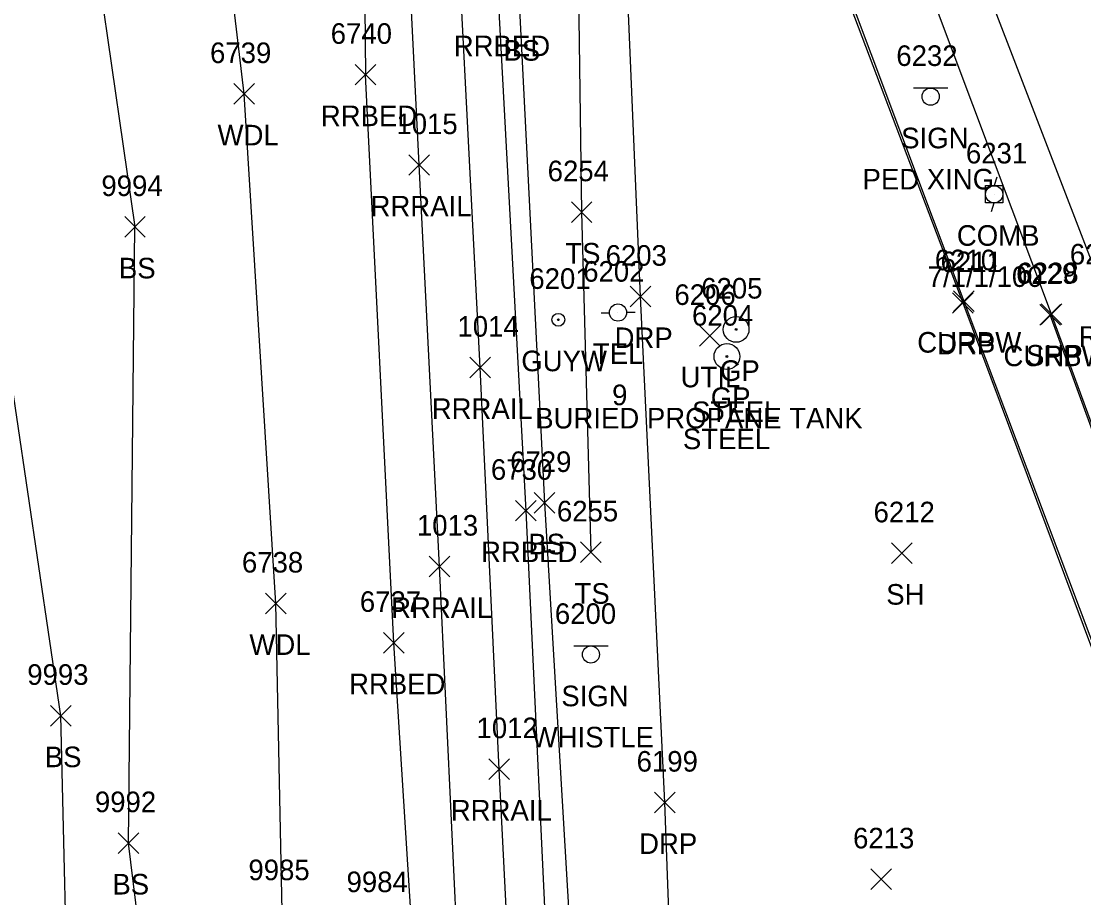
# Model space of a CAD drawing. Extents: x 1769141 to 1770817, y 735471 to 742405.
# Drawn here: x 1770145.7 to 1770248.9, y 740592.3 to 740677.5 of the extents above; entities that cross this region are included whole.
import ezdxf

# ---------------------------------------------------------------- set-up
doc = ezdxf.new("R2010")
doc.units = 0
for name, color, linetype in [('L_A', 7, 'Continuous'), ('L_I', 7, 'Continuous'), ('L_TIC', 7, 'Continuous'), ('LAWA', 7, 'Continuous'), ('LELB', 7, 'Continuous'), ('P_A', 7, 'Continuous'), ('P_I', 7, 'Continuous'), ('P_TIC', 7, 'Continuous'), ('PET', 7, 'Continuous'), ('PSP', 7, 'Continuous'), ('R_A', 7, 'Continuous'), ('R_C', 7, 'Continuous'), ('R_I', 7, 'Continuous'), ('R_TIC', 7, 'Continuous'), ('RC', 7, 'Continuous'), ('RDP', 7, 'Continuous'), ('RGP', 7, 'Continuous'), ('RR', 7, 'Continuous'), ('RRB', 7, 'Continuous'), ('S_A', 7, 'Continuous'), ('S_C', 7, 'Continuous'), ('S_I', 7, 'Continuous'), ('SSGN', 7, 'Continuous'), ('U_A', 7, 'Continuous'), ('U_C', 7, 'Continuous'), ('U_I', 7, 'Continuous'), ('UDEFAULT', 7, 'Continuous'), ('UP', 7, 'Continuous'), ('UPGW', 7, 'Continuous')]:
    doc.layers.add(name, color=color, linetype=linetype)

msp = doc.modelspace()

# ---------------------------------------------------------------- linework, layer by layer
at = {"layer": 'L_TIC'}
for points in [[(1770166.36, 740669.43), (1770168.36, 740671.43)], [(1770168.36, 740669.43), (1770166.36, 740671.43)], [(1770199.14, 740657.95), (1770201.14, 740659.95)], [(1770201.14, 740657.95), (1770199.14, 740659.95)], [(1770155.76, 740656.51), (1770157.76, 740658.51)], [(1770157.76, 740656.51), (1770155.76, 740658.51)], [(1770195.52, 740629.7), (1770197.52, 740631.7)], [(1770197.52, 740629.7), (1770195.52, 740631.7)], [(1770200.04, 740624.9), (1770202.04, 740626.9)], [(1770202.04, 740624.9), (1770200.04, 740626.9)], [(1770230.23, 740624.81), (1770232.23, 740626.81)], [(1770232.23, 740624.81), (1770230.23, 740626.81)], [(1770169.45, 740619.93), (1770171.45, 740621.93)], [(1770171.45, 740619.93), (1770169.45, 740621.93)], [(1770148.56, 740609.02), (1770150.56, 740611.02)], [(1770150.56, 740609.02), (1770148.56, 740611.02)], [(1770155.13, 740596.65), (1770157.13, 740598.65)], [(1770157.13, 740596.65), (1770155.13, 740598.65)], [(1770228.24, 740593.13), (1770230.24, 740595.13)], [(1770230.24, 740593.13), (1770228.24, 740595.13)]]:
    msp.add_lwpolyline(points, dxfattribs=at)
at = {"layer": 'LAWA'}
for points in [[(1770170.45, 740620.93), (1770167.36, 740670.43), (1770162.83, 740708.7)], [(1770171.04, 740591.04), (1770170.45, 740620.93)]]:
    msp.add_lwpolyline(points, dxfattribs=at)
at = {"layer": 'LELB'}
for points in [[(1770196.32, 740733.48), (1770199.58, 740698.98), (1770200.14, 740658.95), (1770201.04, 740625.9)], [(1770192.19, 740728.03), (1770194.1, 740678.66), (1770196.52, 740630.7), (1770199.66, 740577.68), (1770202.23, 740519.28)], [(1770148.83, 740712.41), (1770156.76, 740657.51)], [(1770167.07, 740363.73), (1770164.66, 740417.49), (1770161.1, 740489.86), (1770161.79, 740535.19), (1770159.99, 740566.3), (1770156.13, 740597.65), (1770156.76, 740657.51)], [(1770157.79, 740363.98), (1770157.08, 740418.77), (1770153.72, 740483.23), (1770148.88, 740537.71), (1770150.37, 740576.07), (1770149.56, 740610.02), (1770143.11, 740653.52)]]:
    msp.add_lwpolyline(points, dxfattribs=at)
at = {"layer": 'P_TIC'}
for points in [[(1770244.76, 740648.04), (1770246.76, 740650.04)], [(1770246.76, 740648.04), (1770244.76, 740650.04)]]:
    msp.add_lwpolyline(points, dxfattribs=at)
at = {"layer": 'PET'}
msp.add_lwpolyline([(1770354.08, 740371.38), (1770337.26, 740416.85), (1770319.32, 740465.72), (1770304.6, 740505.64), (1770288.87, 740548.76), (1770274.11, 740588.9), (1770250.94, 740650.86), (1770225.28, 740717.64)], dxfattribs=at)
at = {"layer": 'PSP'}
msp.add_lwpolyline([(1770346.98, 740368.28), (1770329.75, 740414.99), (1770313.12, 740462.55), (1770298.15, 740502.39), (1770298.12, 740506.76), (1770283.52, 740546.61), (1770275.49, 740567.79), (1770273.86, 740568.65), (1770259.2, 740607.52), (1770260.25, 740609.6), (1770245.76, 740649.04), (1770220.84, 740715.43)], dxfattribs=at)
at = {"layer": 'R_TIC'}
for points in [[(1770178.16, 740671.3), (1770180.16, 740673.3)], [(1770180.16, 740671.3), (1770178.16, 740673.3)], [(1770183.35, 740662.53), (1770185.35, 740664.53)], [(1770185.35, 740662.53), (1770183.35, 740664.53)], [(1770204.85, 740649.74), (1770206.85, 740651.74)], [(1770206.85, 740649.74), (1770204.85, 740651.74)], [(1770236.17, 740649.12), (1770238.17, 740651.12)], [(1770238.17, 740649.12), (1770236.17, 740651.12)], [(1770236.26, 740649.3), (1770238.26, 740651.3)], [(1770238.26, 740649.3), (1770236.26, 740651.3)], [(1770244.65, 740647.98), (1770246.65, 740649.98)], [(1770246.65, 740647.98), (1770244.65, 740649.98)], [(1770189.28, 740642.85), (1770191.28, 740644.85)], [(1770191.28, 740642.85), (1770189.28, 740644.85)], [(1770193.72, 740628.94), (1770195.72, 740630.94)], [(1770195.72, 740628.94), (1770193.72, 740630.94)], [(1770185.34, 740623.52), (1770187.34, 740625.52)], [(1770187.34, 740623.52), (1770185.34, 740625.52)], [(1770180.91, 740616.11), (1770182.91, 740618.11)], [(1770182.91, 740616.11), (1770180.91, 740618.11)], [(1770191.14, 740603.84), (1770193.14, 740605.84)], [(1770193.14, 740603.84), (1770191.14, 740605.84)], [(1770207.23, 740600.59), (1770209.23, 740602.59)], [(1770209.23, 740600.59), (1770207.23, 740602.59)]]:
    msp.add_lwpolyline(points, dxfattribs=at)
at = {"layer": 'RC'}
msp.add_lwpolyline([(1770222.17, 740690.52), (1770237.26, 740650.3), (1770253.55, 740607.02), (1770255.1, 740606.24), (1770259.18, 740607.6), (1770260.09, 740609.4), (1770245.65, 740648.98)], dxfattribs=at)
at = {"layer": 'RDP'}
msp.add_lwpolyline([(1770231.87, 740521.7), (1770212.9, 740515.59), (1770209.69, 740561.92), (1770208.23, 740601.59), (1770205.85, 740650.74), (1770204.34, 740686.71), (1770221.92, 740690.38), (1770237.17, 740650.12), (1770253.28, 740606.93), (1770255.09, 740605.92), (1770259.2, 740607.52)], dxfattribs=at)
at = {"layer": 'RGP'}
for p, q in [((1770215.14, 740647.55), (1770215.14, 740647.55)), ((1770214.25, 740644.92), (1770214.25, 740644.92))]:
    msp.add_line(p, q, dxfattribs=at)
for centre, radius in [((1770215.14, 740647.55), 1.25), ((1770215.14, 740647.55), 0.0833), ((1770214.25, 740644.92), 1.25), ((1770214.25, 740644.92), 0.0833)]:
    msp.add_circle(centre, radius, dxfattribs=at)
at = {"layer": 'RR'}
for points in [[(1770197.75, 740390.49), (1770195.85, 740429.49), (1770193.92, 740468.48), (1770191.99, 740507.45), (1770190.02, 740546.42), (1770188.18, 740585.45), (1770186.34, 740624.52), (1770184.35, 740663.53), (1770182.41, 740702.58), (1770181.02, 740730.45), (1770179.25, 740766.27), (1770177.16, 740810.3), (1770173.74, 740877.11), (1770171.32, 740927.71), (1770169.45, 740967.98), (1770167.61, 741006.36), (1770166.54, 741027.4), (1770165.65, 741046.21), (1770163.84, 741084.65), (1770161.66, 741123.76), (1770160.41, 741153.19), (1770158.42, 741192.16), (1770156.87, 741228.02)], [(1770203.66, 740370.75), (1770201.77, 740409.67), (1770199.78, 740448.72), (1770197.9, 740487.78), (1770195.96, 740526.73), (1770194.09, 740565.77), (1770192.14, 740604.84), (1770190.28, 740643.85), (1770188.29, 740682.87), (1770186.41, 740721.83), (1770184.15, 740770), (1770182.62, 740801.29), (1770179.63, 740862.12), (1770176.86, 740918.91), (1770174.1, 740971.71), (1770172.22, 741013.51), (1770171.36, 741030.47), (1770170.33, 741051.22), (1770168.96, 741081.09), (1770166.99, 741119.98), (1770165.66, 741147.29), (1770164.69, 741163.32), (1770164.28, 741173.16), (1770162.44, 741212.29)]]:
    msp.add_lwpolyline(points, dxfattribs=at)
at = {"layer": 'RRB'}
for points in [[(1770189.63, 740726.96), (1770192.08, 740679.1), (1770194.72, 740629.94), (1770197.16, 740578.37), (1770199.02, 740518.43)], [(1770178.78, 740708.43), (1770179.16, 740672.3)], [(1770188.42, 740518.15), (1770185.18, 740565.31), (1770181.91, 740617.11), (1770179.16, 740672.3)]]:
    msp.add_lwpolyline(points, dxfattribs=at)
at = {"layer": 'SSGN'}
for p, q in [((1770232.38, 740671.01), (1770235.71, 740671.01)), ((1770234.03, 740670.17), (1770234.03, 740670.17)), ((1770199.39, 740616.8), (1770202.72, 740616.8)), ((1770201.04, 740615.97), (1770201.04, 740615.97))]:
    msp.add_line(p, q, dxfattribs=at)
for centre in [(1770234.03, 740670.17), (1770201.04, 740615.97)]:
    msp.add_circle(centre, 0.833, dxfattribs=at)
at = {"layer": 'UDEFAULT'}
for points in [[(1770211.59, 740645.93), (1770213.59, 740647.93)], [(1770213.59, 740645.93), (1770211.59, 740647.93)]]:
    msp.add_lwpolyline(points, dxfattribs=at)
at = {"layer": 'UP'}
for p, q in [((1770240.45, 740662.35), (1770240.2, 740661.52)), ((1770239.36, 740659.85), (1770239.36, 740661.52)), ((1770239.36, 740661.52), (1770241.03, 740661.52)), ((1770241.03, 740661.52), (1770241.03, 740659.85)), ((1770241.03, 740659.85), (1770239.36, 740659.85)), ((1770239.95, 740659.02), (1770240.2, 740659.85)), ((1770240.2, 740660.68), (1770240.2, 740660.68)), ((1770202.02, 740649.18), (1770202.84, 740649.18)), ((1770203.67, 740649.19), (1770203.67, 740649.19)), ((1770205.34, 740649.19), (1770204.51, 740649.19)), ((1770204.51, 740649.19), (1770204.51, 740649.19)), ((1770205.34, 740649.19), (1770205.34, 740649.19))]:
    msp.add_line(p, q, dxfattribs=at)
for centre in [(1770240.2, 740660.68), (1770203.67, 740649.19)]:
    msp.add_circle(centre, 0.833, dxfattribs=at)
at = {"layer": 'UPGW'}
for radius in [0.625, 0.0833]:
    msp.add_circle((1770197.88, 740648.49), radius, dxfattribs=at)

# ---------------------------------------------------------------- texts
at = {"layer": 'L_A'}
for s, p in [('BS', (1770192.54, 740673.66)), ('WDL', (1770164.78, 740665.43)), ('TS', (1770198.55, 740653.95)), ('BS', (1770155.2, 740652.51)), ('BS', (1770194.96, 740625.7)), ('TS', (1770199.45, 740620.9)), ('SH', (1770229.72, 740620.81)), ('WDL', (1770167.87, 740615.93)), ('BS', (1770148, 740605.02)), ('BS', (1770154.57, 740592.65))]:
    msp.add_text(s, height=2, dxfattribs=at).set_placement(p)
at = {"layer": 'L_I'}
for s, p in [('6739', (1770164.05, 740673.43)), ('6254', (1770196.84, 740661.95)), ('9994', (1770153.5, 740660.51)), ('6729', (1770193.2, 740633.7)), ('6255', (1770197.74, 740628.9)), ('6212', (1770228.49, 740628.81)), ('6738', (1770167.15, 740623.93)), ('9993', (1770146.3, 740613.02)), ('9992', (1770152.87, 740600.65)), ('6213', (1770226.5, 740597.13)), ('9985', (1770167.78, 740594.04)), ('9984', (1770177.31, 740592.88))]:
    msp.add_text(s, height=2, dxfattribs=at).set_placement(p)
at = {"layer": 'P_A'}
for s, p in [('RDP', (1770248.43, 740645.86)), ('SHP', (1770243.3, 740644.04))]:
    msp.add_text(s, height=2, dxfattribs=at).set_placement(p)
at = {"layer": 'P_I'}
for s, p in [('6230', (1770247.55, 740653.86)), ('6228', (1770242.45, 740652.04))]:
    msp.add_text(s, height=2, dxfattribs=at).set_placement(p)
at = {"layer": 'R_A'}
for s, p in [('RRBED', (1770187.72, 740674.1)), ('RRBED', (1770174.81, 740667.3)), ('RRRAIL', (1770179.64, 740658.53)), ('DRP', (1770203.34, 740645.74)), ('CURBW', (1770232.73, 740645.3)), ('DRP', (1770234.66, 740645.12)), ('CURBW', (1770241.11, 740643.98)), ('GP', (1770213.57, 740642.55)), ('GP', (1770212.68, 740639.92)), ('RRRAIL', (1770185.58, 740638.85)), ('RRBED', (1770190.37, 740624.94)), ('RRRAIL', (1770181.64, 740619.52)), ('RRBED', (1770177.55, 740612.11)), ('RRRAIL', (1770187.43, 740599.84)), ('DRP', (1770205.72, 740596.59))]:
    msp.add_text(s, height=2, dxfattribs=at).set_placement(p)
at = {"layer": 'R_C'}
for p in [(1770210.86, 740638.55), (1770209.97, 740635.92)]:
    msp.add_text('STEEL', height=2, dxfattribs=at).set_placement(p)
at = {"layer": 'R_I'}
for s, p in [('6740', (1770175.77, 740675.3)), ('1015', (1770182.15, 740666.53)), ('6203', (1770202.47, 740653.74)), ('6210', (1770234.44, 740653.3)), ('6211', (1770235, 740653.12)), ('6229', (1770242.33, 740651.98)), ('6205', (1770211.75, 740650.55)), ('6204', (1770210.86, 740647.92)), ('1014', (1770188.08, 740646.85)), ('6730', (1770191.33, 740632.94)), ('1013', (1770184.14, 740627.52)), ('6737', (1770178.6, 740620.11)), ('1012', (1770189.93, 740607.84)), ('6199', (1770205.48, 740604.59))]:
    msp.add_text(s, height=2, dxfattribs=at).set_placement(p)
at = {"layer": 'S_A'}
for p in [(1770231.17, 740665.15), (1770198.17, 740610.94)]:
    msp.add_text('SIGN', height=2, dxfattribs=at).set_placement(p)
at = {"layer": 'S_C'}
for s, p in [('PED XING', (1770227.42, 740661.15)), ('WHISTLE', (1770195.28, 740606.94))]:
    msp.add_text(s, height=2, dxfattribs=at).set_placement(p)
at = {"layer": 'S_I'}
for s, p in [('6232', (1770230.7, 740673.15)), ('6200', (1770197.54, 740618.94))]:
    msp.add_text(s, height=2, dxfattribs=at).set_placement(p)
at = {"layer": 'U_A'}
for s, p in [('COMB', (1770236.58, 740655.68)), ('GUYW', (1770194.28, 740643.49)), ('TEL', (1770201.23, 740644.19)), ('UTIL', (1770209.75, 740641.93))]:
    msp.add_text(s, height=2, dxfattribs=at).set_placement(p)
at = {"layer": 'U_C'}
for s, p in [('7/1/1/100', (1770233.75, 740651.68)), ('9', (1770203.1, 740640.19)), ('BURIED PROPANE TANK', (1770195.63, 740637.93))]:
    msp.add_text(s, height=2, dxfattribs=at).set_placement(p)
at = {"layer": 'U_I'}
for s, p in [('6231', (1770237.46, 740663.68)), ('6202', (1770200.29, 740652.19)), ('6201', (1770195.06, 740651.49)), ('6206', (1770209.15, 740649.93))]:
    msp.add_text(s, height=2, dxfattribs=at).set_placement(p)

doc.saveas('drawing.dxf')
